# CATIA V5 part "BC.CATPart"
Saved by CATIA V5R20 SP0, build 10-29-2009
Part number: BC
Bounding box of the stored display mesh (mm): x -15 to 5, y -80 to 180, z -5 to 15
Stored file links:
  C:\Users\Willy\Documents\ThinkMotion\1691\BC.CATPart
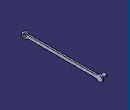
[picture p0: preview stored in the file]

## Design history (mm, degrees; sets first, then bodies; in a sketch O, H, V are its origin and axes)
Parameters
  `Longueur bièle` = 240 mm
Body1 (main body)
  Sketch1 on yz-plane, origin (0, 0, 0), H (0, 1, 0), V (0, 0, 1)
    line L1 (-70, 15) -> (170, 15)
    line L2 (170, -5) -> (-70, -5)
    point P2 (170, 15)
    point P3 (170, -5)
    point P4 (-70, -5)
    arc A1 centre (170, 5) radius 10 from (170, -5) to (170, 15) ccw
    point P5 (170, 5)
    arc A2 centre (-70, 5) radius 10 from (-70, 15) to (-70, -5) ccw
    point P6 (-70, 5)
    construction line L3 (-70, 30) -> (-70, -30)
    axis line L4 (170, 35) -> (170, -35)
    circle A3 centre (-70, 5) radius 5
    point P11 (-70, 0)
    circle A4 centre (170, 5) radius 5
    length L1 = 240 {= `Longueur bièle`}
    radius A4 = 5
    radius A3 = 5
    distance L1 L2 = 20
    horizontal: L1 H, L2 H
    tangency: A2 L1
    vertical: L3 V, L4 V
    coincidence: P6 L3, P4 L3, P3 L4, P5 L4, P2 L4, A3 P11, P11 H
  Pad1: profile Sketch1, direction (1, 0, 0), length 5
  Sketch2 on start face of Pad1, origin (0, 0, 0), H (0, -1, 0), V (0, 0, 1)
    circle A1 centre (-170, 5) radius 5
    reference projected circle E1 centre (-170, 5) radius 5 from edge [face of Pad1 from Sketch1.A4 | start face of Pad1]
    coincidence: A1 E1
  Pad2: profile Sketch2, direction (-1, 0, 0), length 15, opposite side length 5
  Sketch3 on face of Pad2, origin (5, 0, 0), H (0, 1, 0), V (0, 0, 1)
    arc A1 centre (-70, 5) radius 10 from (-70, -5) to (-61.3397, 0) ccw
    reference projected arc E1 centre (-70, 5) radius 10 from (-70, 15) to (-70, -5) ccw from edge [face of Pad1 from Sketch1.A2 | end face of Pad1]
    arc A2 centre (170, 5) radius 10 from (161.3397, 0) to (170, -5) ccw
    reference projected arc E2 centre (170, 5) radius 10 from (170, -5) to (170, 15) ccw from edge [face of Pad1 from Sketch1.A1 | end face of Pad1]
    line L1 (-70, -5) -> (170, -5)
    line L2 (-70, 15) -> (170, 15)
    point P6 (170, 15)
    line L3 (-61.3397, 0) -> (161.3397, 0)
    line L4 (-61.3397, 10) -> (161.3397, 10)
    point P9 (-61.3397, 10)
    arc A3 centre (170, 5) radius 10 from (170, 15) to (161.3397, 10) ccw
    arc A4 centre (-70, 5) radius 10 from (-61.3397, 10) to (-70, 15) ccw
    distance L3 L1 = 5
    coincidence: A1 E1, E2 A2, P6 A2, P9 A1, A2 A3, A1 A4
    tangency: L1 A2, L2 A2
    horizontal: L3 H, L4 H
  Pocket1: profile Sketch3, direction (-1, 0, 0), length 15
